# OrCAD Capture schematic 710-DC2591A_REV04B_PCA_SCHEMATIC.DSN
size Custom; note: EasySMU
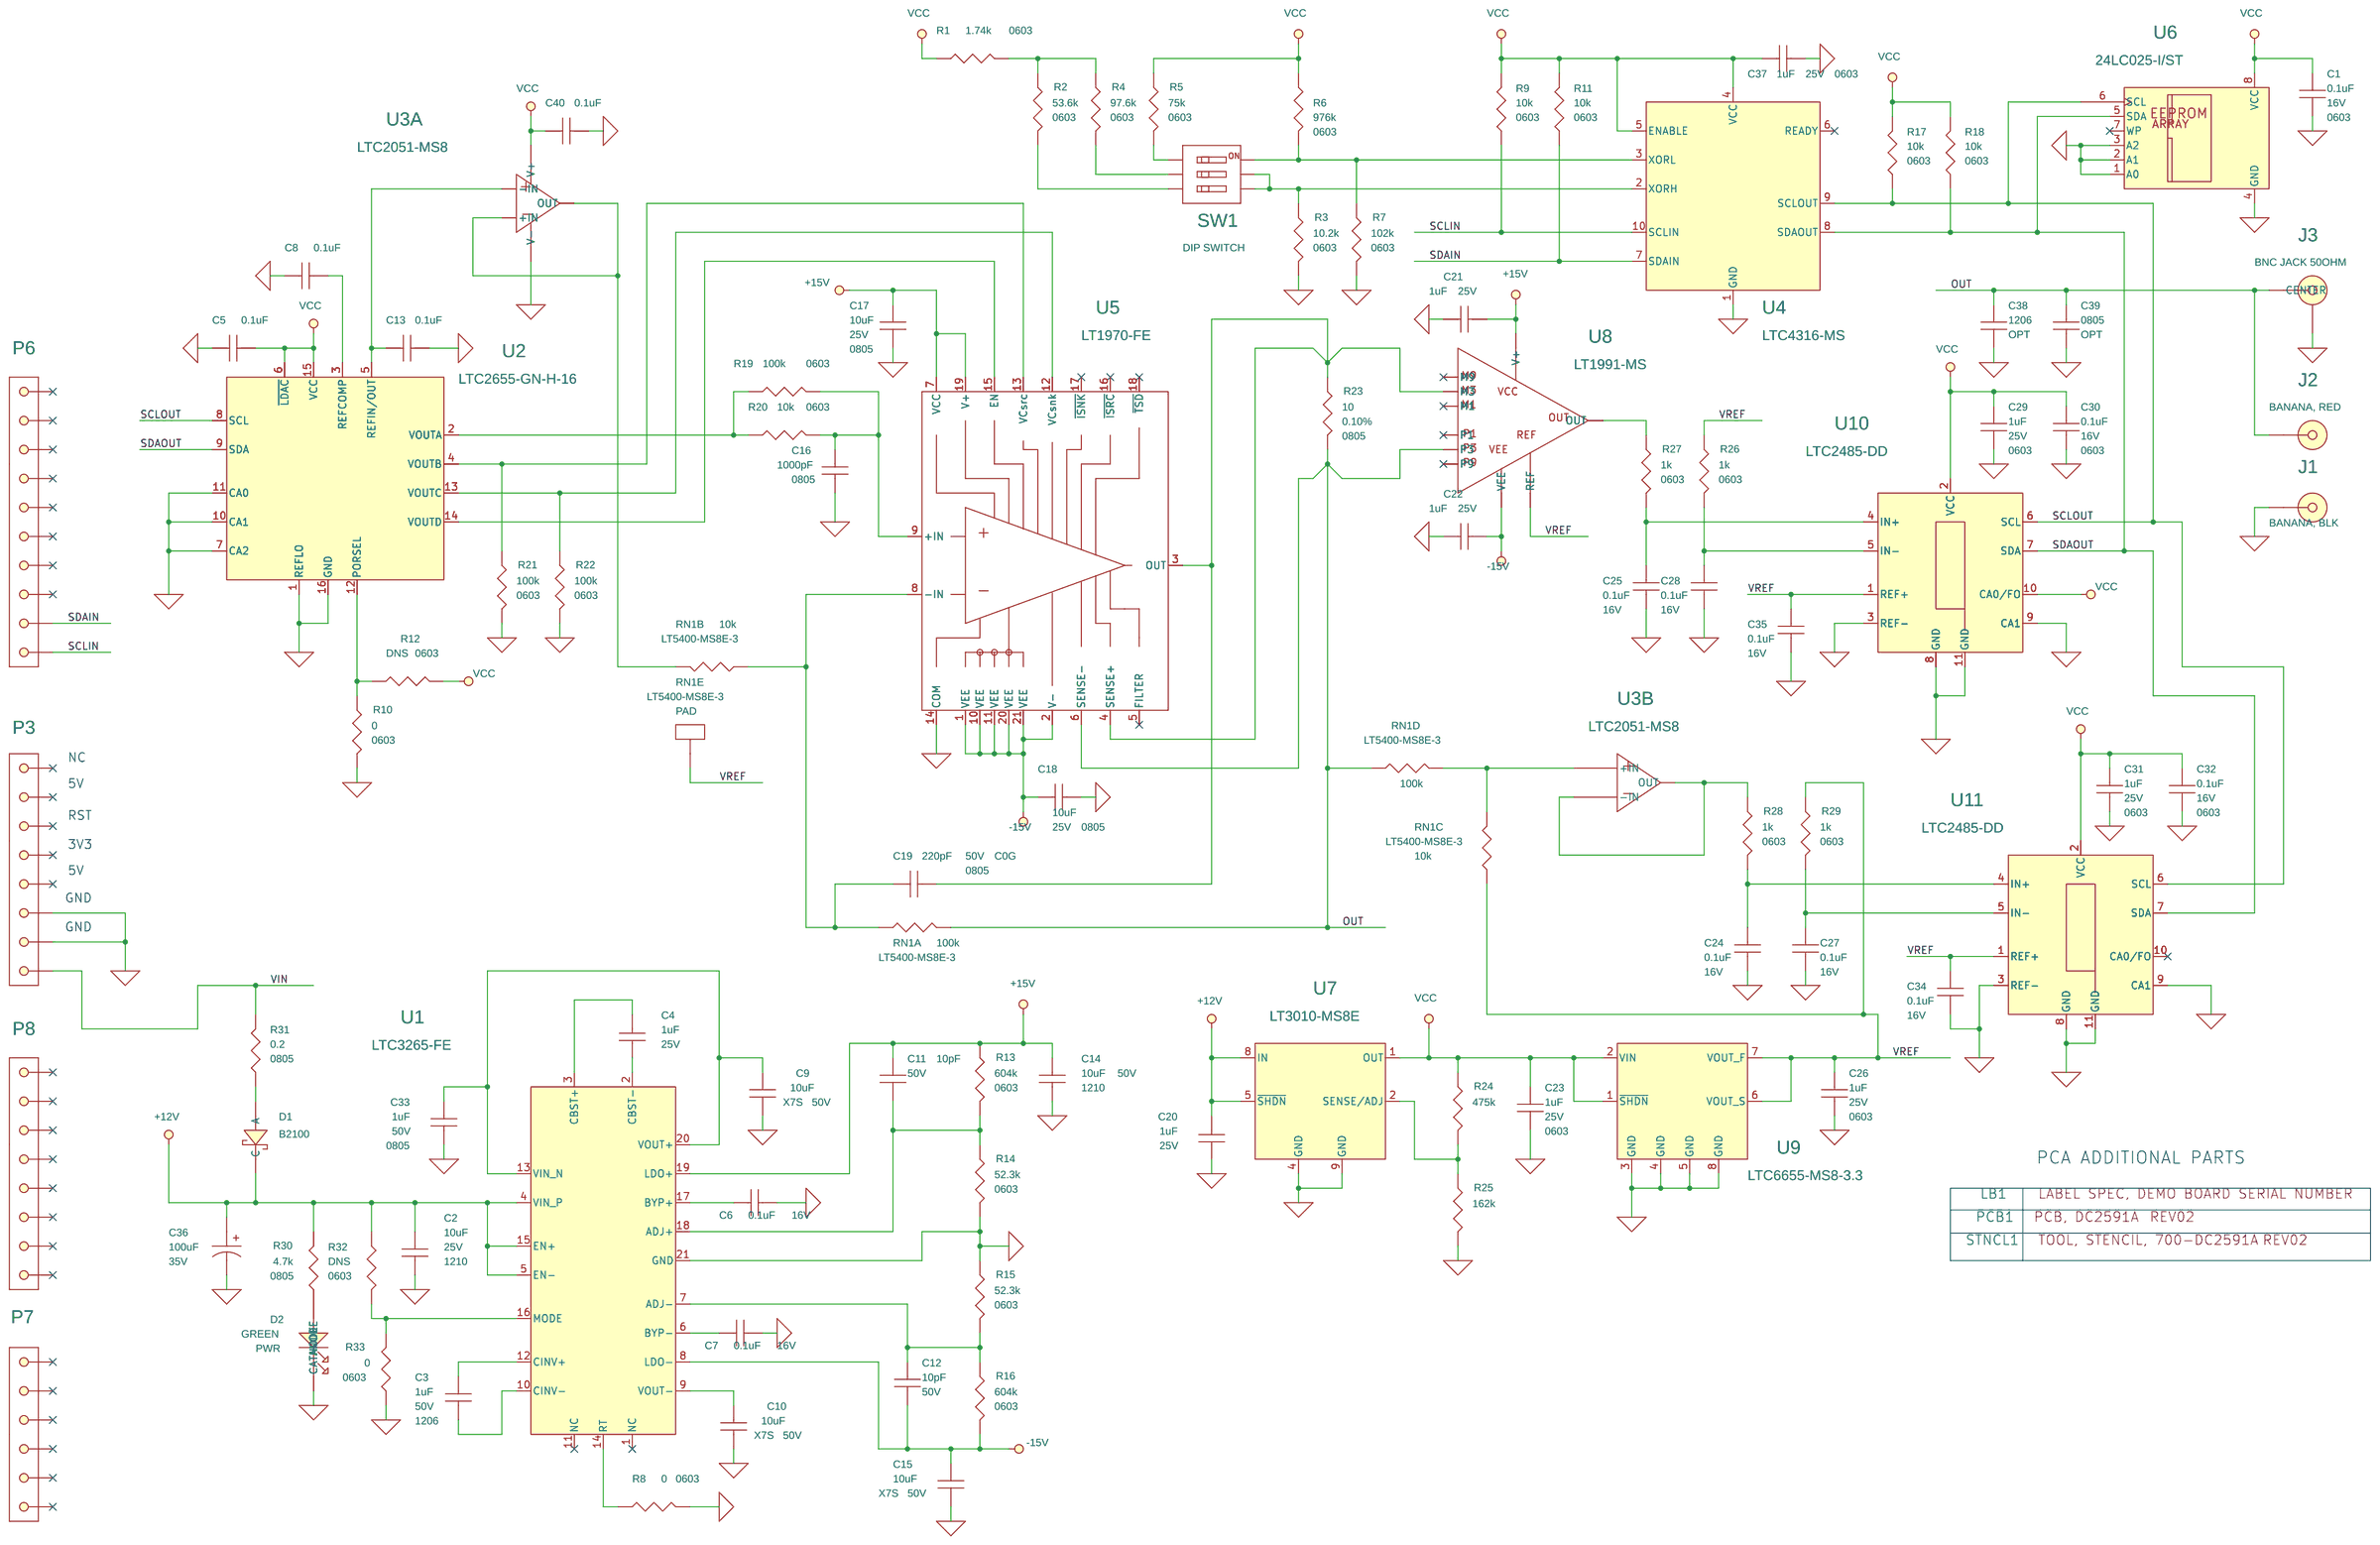
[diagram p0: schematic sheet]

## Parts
C1  0.1uF  [CC0603N]
C2  10uF  [CC1210N]
C3  1uF  [CC1206N]
C4  1uF  [CC0805N]
C5  0.1uF  [CC0603N]
C6  0.1uF  [CC0603N]
C7  0.1uF  [CC0603N]
C8  0.1uF  [CC0603N]
C9  10uF  [CC1210N]
C10  10uF  [CC1210N]
C11  10pF  [CC0603N]
C12  10pF  [CC0603N]
C13  0.1uF  [CC0603N]
C14  10uF  [CC1210N]
C15  10uF  [CC1210N]
C16  1000pF  [CC0805N]
C17  10uF  [CC0805N]
C18  10uF  [CC0805N]
C19  220pF  [CC0805N]
C20  1uF  [CC0805N]
C21  1uF  [CC0603N]
C22  1uF  [CC0603N]
C23  1uF  [CC0603N]
C24  0.1uF  [CC0603N]
C25  0.1uF  [CC0603N]
C26  1uF  [CC0603N]
C27  0.1uF  [CC0603N]
C28  0.1uF  [CC0603N]
C29  1uF  [CC0603N]
C30  0.1uF  [CC0603N]
C31  1uF  [CC0603N]
C32  0.1uF  [CC0603N]
C33  1uF  [CC0805N]
C34  0.1uF  [CC0603N]
C35  0.1uF  [CC0603N]
C36  100uF  [SUNCON_HVP_8X10.5]
C37  1uF  [CC0603N]
C38  OPT  [CC1206N]
C39  OPT  [CC0805N]
C40  0.1uF  [CC0603N]
D1  B2100  [DIODESINC-SMB]
D2  GREEN  [LED_0805]
J1  JACK SOCKET BLACK  [MULTI-CONTACT_SLB4-I/90]
J2  JACK SOCKET RED  [MULTI-CONTACT_SLB4-I/90]
J3  BNC JACK 50OHM  [MOLEX-73137-5003]
LB1  LABEL  [895-0154_REV01]
P3  HDR  [HD1X8-100]
P6  HDR  [HD1X10-100]
P7  HDR  [HD1X6-100]
P8  HDR  [HD1X8-100]
PCB1  PCB, DC2591A
R1  1.74k  [CR0603N]
R2  53.6k  [CR0603N]
R3  10.2k  [CR0603N]
R4  97.6k  [CR0603N]
R5  75k  [CR0603N]
R6  976k  [CR0603N]
R7  102k  [CR0603N]
R8  0  [CR0603N]
R9  10k  [CR0603N]
R10  0  [CR0603N]
R11  10k  [CR0603N]
R12  OPT  [CR0603N]
R13  604k  [CR0603N]
R14  52.3k  [CR0603N]
R15  52.3k  [CR0603N]
R16  604k  [CR0603N]
R17  10k  [CR0603N]
R18  10k  [CR0603N]
R19  100k  [CR0603N]
R20  10k  [CR0603N]
R21  100k  [CR0603N]
R22  100k  [CR0603N]
R23  10  [CR0805N]
R24  475k  [CR0805N]
R25  162k  [CR0805N]
R26  1k  [CR0603N]
R27  1k  [CR0603N]
R28  1k  [CR0603N]
R29  1k  [CR0603N]
R30  4.7k  [CR0805N]
R31  0.2  [CR0805N]
R32  OPT  [CR0603N]
R33  0  [CR0603N]
RN1  LT5400-MS8E-3  [LTC-MS8E-8-1662]  (sections A,B,C,D,E)
STNCL1  TOOL, STENCIL, 700-DC2591A
SW1  SPST  [CTS-219-3]
U1  LTC3265-FE  [LTC-FE-20-1663(CA)]
U2  LTC2655-GN-H-16  [LTC-GN-16-1641(GN16)]
U3  LTC2051-MS8  [LTC-MS8-8-1660]  (sections A,B)
U4  LTC4316-MS  [LTC-MS-10-1661]
U5  LT1970-FE  [LTC-FE-20-1663(CA)]
U6  24LC025-I/ST  [MICROCHIP-TSSOP-8]
U7  LT3010-MS8E  [LTC-MS8E-8-1662]
U8  LT1991-MS  [LTC-MS-10-1661]
U9  LTC6655-MS8-3.3  [LTC-MS8-8-1660]
U10  LTC2485-DD  [LTC-DD-10-1699]
U11  LTC2485-DD  [LTC-DD-10-1699]

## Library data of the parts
C1 C6 C7 C24 C25 C27 C28 C30 C32 C34 C35 = CAP: CAP.,0.1uF,X7R,16V,10%,0603; CLASS: DISCRETE; Dielectric Type: X7R; FPLIST: CC0603N,CC0603L,CC0603M; Manufacturer: MURATA; Manufacturer PN: GRM188R71C104KA01D; PART_NUMBER: 150-0018; Package Size: 0603; Package Type: SMD; Rated Voltage: 16V; Tolerance: 10%
C2 = CAP: CAP.,10uF,X7R,25V,10%,1210; CLASS: DISCRETE; Dielectric Type: X7R; FPLIST: CC1210N,CC1210L,CC1210M; Manufacturer: MURATA; Manufacturer PN: GRM32DR71E106KA12L; PART_NUMBER: 150-0282; Package Size: 1210; Rated Voltage: 25V; Tolerance: 10%
C3 = CAP: CAP.,1uF,X7R,50V,10%,1206; CLASS: DISCRETE; Dielectric Type: X7R; FPLIST: CC1206N,CC1206L,CC1206M; Manufacturer: MURATA; Manufacturer PN: GRM31MR71H105KA88L; PART_NUMBER: 150-3089; Package Size: 1206; Rated Voltage: 50V; Tolerance: 10%
C4 C20 = CAP: CAP.,1uF,X7R,25V,10%,0805; CLASS: DISCRETE; Dielectric Type: X7R; FPLIST: CC0805N,CC0805L,CC0805M; Manufacturer: AVX; Manufacturer PN: 08053C105KAT2A; PART_NUMBER: 150-3037; Package Size: 0805; Rated Voltage: 25V; Tolerance: 10%
C5 C8 C13 C40 = CAP: CAP.,0.1uF,X7R,16V,10%,0603; CLASS: DISCRETE; Dielectric Type: X7R; FPLIST: CC0603N,CC0603L,CC0603M; Manufacturer: AVX; Manufacturer PN: 0603YC104KAT2A; PART_NUMBER: 150-0164; Package Size: 0603; Package Type: SMD; Rated Voltage: 16V; Tolerance: 10%
C9 C10 C15 = CAP: CAP.,10uF,X7S,50V,10%,1210; CLASS: DISCRETE; Dielectric Type: X7S; Manufacturer: TDK; Manufacturer PN: C3225X7S1H106K250AB; PART_NUMBER: 150-3091; Package Size: 1210; Rated Voltage: 50V; Tolerance: 10%
C11 C12 = CAP: CAP.,10pF,NP0,50V,5%,0603; CLASS: DISCRETE; Dielectric Type: NP0; FPLIST: CC0603N,CC0603L,CC0603M; Manufacturer: NIC; Manufacturer PN: NMC0603NPO100J50TRPF; PART_NUMBER: 150-3504; Package Size: 0603; Rated Voltage: 50V; Tolerance: 5%
C14 = CAP: CAP.,10uF,X7R,50V,10%,1210; CLASS: DISCRETE; Dielectric Type: X7R; Manufacturer: MURATA; Manufacturer PN: GRM32ER71H106KA12L; PART_NUMBER: 150-3043; Package Size: 1210; Package Type: SMD; Rated Voltage: 50V; Tolerance: 10%
C16 = CAP: CAP.,1000pF,X7R,50V,5%,0805; CLASS: DISCRETE; Dielectric Type: X7R; FPLIST: CC0805N,CC0805L,CC0805M; Manufacturer: AVX; Manufacturer PN: 08055C102JAT2A; PART_NUMBER: 150-0582; Package Size: 0805; Rated Voltage: 50V; Tolerance: 5%
C17 C18 = CAP: CAP.,10uF,X5R,25V,10%,0805; CLASS: DISCRETE; Dielectric Type: X5R; FPLIST: CC0805N,CC0805L,CC0805M; Manufacturer: MURATA; Manufacturer PN: GRM21BR61E106KA73L; PART_NUMBER: 150-3405; Package Size: 0805; Package Type: SMD; Rated Voltage: 25V; Tolerance: 10%; UserField01: Thickness = 1.25 +/-0.15mm
C19 = CAP: CAP.,220pF,C0G,50V,5%,0805; CLASS: DISCRETE; Dielectric Type: C0G; FPLIST: CC0805N,CC0805L,CC0805M; Manufacturer: AVX; Manufacturer PN: 08055A221JAT2A; PART_NUMBER: 150-3424; Package Size: 0805; Rated Voltage: 50V; Tolerance: 5%
C21-C23 C26 C29 C31 C37 = CAP: CAP.,1uF,X5R,25V,10%,0603; CLASS: DISCRETE; Dielectric Type: X5R; FPLIST: CC0603N,CC0603L,CC0603M; Manufacturer: MURATA; Manufacturer PN: GRM188R61E105KA12D; PART_NUMBER: 150-0247; Package Size: 0603; Rated Voltage: 25V; Tolerance: 10%
C33 = CAP: CAP.,1uF,X7R,50V,10%,0805; CLASS: DISCRETE; Dielectric Type: X7R; FPLIST: CC0805N,CC0805L,CC0805M; Manufacturer: MURATA; Manufacturer PN: GRM21BR71H105KA12L; PART_NUMBER: 150-3335; Package Size: 0805; Rated Voltage: 50V; Tolerance: 10%
C36 = CAP_P: CAP.,100uF,ALUM.,35V,20%,SMD 8x10.5mm,HVP Series; CLASS: DISCRETE; Dielectric Type: ALUM.; Manufacturer: SUN ELECTRONIC INDUSTRIES CORP; Manufacturer PN: 35HVP100M; PART_NUMBER: 150-2315; Package Size: SMD 8x10.5mm; Rated Voltage: 35V; Tolerance: 20%; UserField01: HVP Series
C38 = CAP: CAP., OPTION, 1206; CLASS: DISCRETE; FPLIST: CC1206N,CC1206L,CC1206M; PART_NUMBER: 150-3160; Package Size: 1206; Package Type: SMD
C39 = CAP: CAP., OPTION, 0805; CLASS: DISCRETE; FPLIST: CC0805N,CC0805L,CC0805M; PART_NUMBER: 150-3036; Package Size: 0805; Package Type: SMD
D1 = DIODE_SCHOTTKY_A: DIODE,SCHOTTKY,100V,2A,SMB,AECQ10x; CLASS: DISCRETE; Manufacturer: DIODES INC; Manufacturer PN: B2100-13-F; PART_NUMBER: 210-0088; Package Size: SMB; Package Type: SMB; Rated Voltage: 100V
D2 = LED: LED,GREEN,DIFFUSED,0805; CLASS: DISCRETE; Manufacturer: BROADCOM LIMITED; Manufacturer PN: HSMG-C170; PART_FIELD_1: PWR; PART_NUMBER: 270-0060; Package Type: 0805
J1 = BANANA_JACK: CONN.,JACK SOCKET BLACK,FEMALE,1 POS,33mm X 12mm,THT HOLE; CLASS: IO; Manufacturer: MULTI-CONTACT; Manufacturer PN: 23.3200-21; PART_FIELD_01: BANANA, BLK; PART_NUMBER: 250-0628
J2 = BANANA_JACK: CONN.,JACK SOCKET RED,FEMALE,1 POS,33mm X 12mm,THT-HOLE; CLASS: IO; Manufacturer: MULTI-CONTACT; Manufacturer PN: 23.3200-22; PART_FIELD_01: BANANA, RED; PART_NUMBER: 250-0627
J3 = BNC_2-PIN: CONN.,BNC JACK 50OHM,FEMALE,35.18mm x 13.2mm,THT, RA; CLASS: IO; Manufacturer: MOLEX; Manufacturer PN: 73137-5003; PART_NUMBER: 250-0634
LB1 = BLANK_LABEL: LABEL SPEC, DEMO BOARD SERIAL NUMBER; Manufacturer: BRADY; Manufacturer PN: THT-96-717-10; PART_NUMBER: 895-0154
P3 P8 = HDR1X8: CONN.,HDR,RECEPT,1X8,2.54mm,THT STR; CLASS: IO; Manufacturer: SAMTEC; Manufacturer PN: SSQ-108-04-G-S; PART_NUMBER: 250-0635
P6 = HDR1X10: CONN.,HDR,RECEPT,1X10,2.54mm,THT STR; CLASS: IO; Manufacturer: SAMTEC; Manufacturer PN: SSQ-110-04-G-S; PART_NUMBER: 250-0636
P7 = HDR1X6: CONN.,HDR,RECEPT,1X6,2.54mm,THT STR; CLASS: IO; Manufacturer: SAMTEC; Manufacturer PN: SSQ-106-04-G-S; PART_NUMBER: 250-0637
PCB1 = BLANK_PCB_PART: BOM Notes: REV02; CLASS: DISCRETE; Manufacturer: MAO BANG; Manufacturer PN: 600-DC2591A; PART_NUMBER: 600-DC2591A
R1 = RES: RES.,1.74k OHMS,1%,1/10W,0603; CLASS: DISCRETE; FPLIST: CR0603N,CR0603L,CR0603M; Manufacturer: YAGEO; Manufacturer PN: 9C06031A1741FKHFT; PART_NUMBER: 100-0135; Package Size: 0603; Rated Power: 1/10W; Tolerance: 1%
R2 = RES: RES.,53.6k OHMS,1%,1/10W,0603; CLASS: DISCRETE; FPLIST: CR0603N,CR0603L,CR0603M; Manufacturer: KOA SPEER; Manufacturer PN: RK73H1JTTD5362F; PART_NUMBER: 100-0233; Package Size: 0603; Rated Power: 1/10W; Temperature Coefficient: 100ppm/C; Tolerance: 1%
R3 = RES: RES.,10.2k OHMS,1%,1/10W,0603; CLASS: DISCRETE; Manufacturer: VISHAY; Manufacturer PN: CRCW060310K2FKEA; PART_NUMBER: 100-0627; Package Size: 0603; Rated Power: 1/10W; Temperature Coefficient: +/-100PPM; Tolerance: 1%
R4 = RES: RES.,97.6k OHMS,1%,1/10W,0603; CLASS: DISCRETE; Manufacturer: VISHAY; Manufacturer PN: CRCW060397K6FKEA; PART_NUMBER: 100-0628; Package Size: 0603; Rated Power: 1/10W; Temperature Coefficient: +/-100PPM; Tolerance: 1%
R5 = RES: RES.,AEC-Q200,75k OHMS,0.1%,1/16W,0603; CLASS: DISCRETE; FPLIST: CR0603N,CR0603L,CR0603M; Manufacturer: SUSUMU CO LTD; Manufacturer PN: RG1608P-753-B-T5.; PART_NUMBER: 100-0159; Package Size: 0603; Rated Power: 1/16W; Temperature Coefficient: 25ppm/C; Tolerance: 0.10%
R6 = RES: RES.,976k OHMS,1%,1/10W,0603; CLASS: DISCRETE; FPLIST: CR0603N,CR0603L,CR0603M; Manufacturer: YAGEO; Manufacturer PN: RC0603FR-07976KL; PART_NUMBER: 100-2619; Package Size: 0603; Rated Power: 1/10W; Temperature Coefficient: 100ppm/C; Tolerance: 1%
R7 = RES: RES.,102k OHMS,1%,1/10W,0603; CLASS: DISCRETE; FPLIST: CR0603N,CR0603L,CR0603M; Manufacturer: NIC; Manufacturer PN: NRC06F1023TRF; PART_NUMBER: 100-2726; Package Size: 0603; Rated Power: 1/10W; Temperature Coefficient: 100ppm/C; Tolerance: 1%
R8 R10 R33 = RES: RES.,0 OHM,1/10W,0603; CLASS: DISCRETE; FPLIST: CR0603N,CR0603L,CR0603M; Manufacturer: VISHAY; Manufacturer PN: CRCW06030000Z0EA; PART_NUMBER: 100-0009; Package Size: 0603; Rated Power: 1/10W
R9 R11 R17 R18 R20 = RES: RES.,10k OHMS,1%,1/10W,0603; CLASS: DISCRETE; FPLIST: CR0603N,CR0603L,CR0603M; Manufacturer: NIC; Manufacturer PN: NRC06F1002TRF; PART_NUMBER: 100-2532; Package Size: 0603; Rated Power: 1/10W; Temperature Coefficient: 100ppm/C; Tolerance: 1%
R12 R32 = RES: RES., OPTION, 0603; CLASS: DISCRETE; FPLIST: CR0603N,CR0603L,CR0603M; PART_FIELD_1: DNS; PART_NUMBER: 100-2374; Package Size: 0603
R13 R16 = RES: RES.,604k OHMS,1%,1/10W,0603; CLASS: DISCRETE; FPLIST: CR0603N,CR0603L,CR0603M; Manufacturer: VISHAY; Manufacturer PN: CRCW0603604KFKEA; PART_NUMBER: 100-2679; Package Size: 0603; Rated Power: 1/10W; Temperature Coefficient: 100ppm; Tolerance: 1%
R14 R15 = RES: RES.,52.3k OHMS,1%,1/10W,0603; CLASS: DISCRETE; FPLIST: CR0603N,CR0603L,CR0603M; Manufacturer: VISHAY; Manufacturer PN: CRCW060352K3FKEA; PART_NUMBER: 100-0346; Package Size: 0603; Rated Power: 1/10W; Temperature Coefficient: 100ppm/C; Tolerance: 1%
R19 R21 R22 = RES: RES.,100k OHMS,1%,1/10W,0603; CLASS: DISCRETE; FPLIST: CR0603N,CR0603L,CR0603M; Manufacturer: NIC; Manufacturer PN: NRC06F1003TRF; PART_NUMBER: 100-0343; Package Size: 0603; Rated Power: 1/10W; Temperature Coefficient: 100ppm; Tolerance: 1%
R23 = RES: RES.,CURRENT SENSE,10 OHMS,0.1%,1/8W,0805; CLASS: DISCRETE; Manufacturer: BOURNS; Manufacturer PN: CRT0805-BY-10R0ELF; PART_NUMBER: 100-0629; Package Size: 0805; Rated Power: 1/8W; Temperature Coefficient: +/-25PPM; Tolerance: 0.10%
R24 = RES: RES.,475k OHMS,1%,1/8W,0805; CLASS: DISCRETE; Manufacturer: YAGEO; Manufacturer PN: RC0805FR-07475KL; PART_NUMBER: 100-0630; Package Size: 0805; Rated Power: 1/8W; Temperature Coefficient: +/-100PPM; Tolerance: 1%
R25 = RES: RES.,162k OHMS,1%,1/8W,0805; CLASS: DISCRETE; Manufacturer: YAGEO; Manufacturer PN: RC0805FR-07162KL; PART_NUMBER: 100-0631; Package Size: 0805; Rated Power: 1/8W; Temperature Coefficient: PPM; Tolerance: 1%
R26-R29 = RES: RES.,1k OHM,1%,1/10W,0603; CLASS: DISCRETE; FPLIST: CR0603N,CR0603L,CR0603M; Manufacturer: NIC; Manufacturer PN: NRC06F1001TRF; PART_NUMBER: 100-2422; Package Size: 0603; Rated Power: 1/10W; Temperature Coefficient: 100ppm; Tolerance: 1%
R30 = RES: RES.,4.7k OHMS,5%,1/8W,0805; CLASS: DISCRETE; FPLIST: CR0805N,CR0805L,CR0805M; Manufacturer: PANASONIC; Manufacturer PN: ERJ6GEYJ472V; PART_NUMBER: 100-2602; Package Size: 0805; Rated Power: 1/8W; Temperature Coefficient: 200ppm/C; Tolerance: 5%
R31 = RES: RES.,NO ALTERNATE MFR P/N ALLOWED,0.2 OHMS,5%,1/4W,0805; CLASS: DISCRETE; Manufacturer: PANASONIC; Manufacturer PN: ERJS6SJR20V; PART_NUMBER: 100-2560; Package Size: 0805; Rated Power: 1/4W; Temperature Coefficient: 150ppm/C; Tolerance: 5%
RN1 = LT5400-MS8E-X_A-E: IC,QUAD RESISTOR NETWORK,8-pin MS8E; CLASS: IC; Manufacturer: LINEAR TECHNOLOGY; Manufacturer PN: LT5400AIMS8E-3#PBF; PART_FIELD_1: 100k; PART_NUMBER: LT5400AIMS8E-3#PBF; Package Size: MS8E; Package Type: 8-pin MS8E; FIRST_PART_FIELD: 100k
STNCL1 = BLANK_STENCIL_PART: BOM Notes: REV02; CLASS: DISCRETE; Manufacturer: LINEAR TECHNOLOGY; Manufacturer PN: 830-DC2591A; PART_NUMBER: 830-DC2591A
SW1 = DIP_SW_3POS: SWITCH,SLIDE DIP,SPST,100MA,20V,THT; CLASS: DISCRETE; Manufacturer: CTS; Manufacturer PN: 219-3MST; PART_FIELD_1: DIP SWITCH; PART_NUMBER: 430-0068; Package Size: 0.358" (9.09mm)
U1 = LTC3265-FE: IC SWITCHED CAPACITOR INVERTING REGULATOR, TSSOP-20; CLASS: IC; Manufacturer: LINEAR TECHNOLOGY; Manufacturer PN: LTC3265IFE#PBF; PART_NUMBER: LTC3265IFE#PBF; Package Size: 20-TSSOP; Package Type: 20-pin TSSOP
U2 = LTC2655-GN-H-X: QUAD 16-BIT DAC; CLASS: IC; Manufacturer: LINEAR TECHNOLOGY; Manufacturer PN: LTC2655BIGN-H16#PBF; PART_NUMBER: LTC2655BIGN-H16#PBF; Package Type: 16-pin NARROW SSOP
U3 = LTC2051-MS8: DUAL ZERO-DRIFT OP AMP; CLASS: IC; Manufacturer: LINEAR TECHNOLOGY; Manufacturer PN: LTC2051IMS8#PBF; PART_NUMBER: LTC2051IMS8#PBF; Package Size: MSOP; Package Type: 8pin MSOP
U4 = LTC4316-MS: IC,I2C/SMBUS TRANSLATOR,MS10; CLASS: IC; Manufacturer: LINEAR TECHNOLOGY; Manufacturer PN: LTC4316IMS#PBF; PART_NUMBER: LTC4316IMS#TRPBF; Package Size: TSOT-23; Package Type: MS10
U5 = LT1970-FE: POWER OP-AMP; CLASS: IC; Manufacturer: LINEAR TECHNOLOGY; Manufacturer PN: LT1970AIFE#PBF; PART_NUMBER: LT1970AIFE#PBF; Package Size: 20-TSSOP; Package Type: 20-pin TSSOP
U6 = 24LC025-I_ST_TSSOP-8_C: IC, MEMORY,EEPROM,2Kb (256x8),TSSOP-8,400kHz; CLASS: IC; Manufacturer: Microchip; PART_NUMBER: 380-0087; Package Size: TSSOP-8; Package Type: TSSOP-8
U7 = LT3010-MS8E-X: IC,LDO uPWR LINEAR REG.,MSOP-8; CLASS: IC; Manufacturer: LINEAR TECHNOLOGY; Manufacturer PN: LT3010EMS8E#PBF; PART_NUMBER: LT3010EMS8E#PBF; Package Size: 20-TSSOP; Package Type: MSOP-8
U8 = LT1991-MS: GAIN-SELECTABLE AMPLIFIER; CLASS: IC; Manufacturer: LINEAR TECHNOLOGY; Manufacturer PN: LT1991AIMS#PBF; PART_NUMBER: LT1991AIMS#PBF; Package Size: MS-10; Package Type: 10-pin MSOP
U9 = LTC6655-MS8-X_ALT1: IC, VOLTAGE REFERENCE, MSOP; CLASS: IC; Manufacturer: LINEAR TECHNOLOGY; Manufacturer PN: LTC6655BHMS8-3.3#PBF; PART_NUMBER: LTC6655BHMS8-3.3#TRPBF; Package Size: MS8; Package Type: 8-pin MSOP
U10 U11 = LTC2485-DD: 24-BiT Delta Sigma ADC; CLASS: IC; Manufacturer: LINEAR TECHNOLOGY; Manufacturer PN: LTC2485IDD#PBF; PART_NUMBER: LTC2485IDD#PBF; Package Type: 10-pin DFN

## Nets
+12V: C2.1 C20.2 C36.1 D1.1(C) R30.1 R32.1 U1.4(VIN_P) U1.5(EN-) U1.15(EN+) U7.5(~{SHDN}) U7.8(IN)
+15V: C11.1 C14.1 C17.1 C21.2 R13.1 U1.19(LDO+) U5.7(VCC) U5.19(V+) U8.7(V+)
-15V: C12.2 C15.1 C18.1 C22.2 R16.2 U1.8(LDO-) U5.1(VEE) U5.2(V-) U5.10(VEE) U5.11(VEE) U5.20(VEE) U5.21(VEE) U8.4(VEE)
GND_SIGNAL: C1.2 C2.2 C5.1 C6.2 C7.2 C8.1 C9.2 C10.2 C13.2 C14.2 C15.2 C16.2 C17.2 C18.2 C20.1 C21.1 C22.1 C23.2 C24.2 C25.2 C26.2 C27.2 C28.2 C29.2 C30.2 C31.2 C32.2 C33.2 C34.2 C35.2 C36.2 C37.2 C38.2 C39.2 C40.2 D2.1(CATHODE) J1.1 J3.2 P3.6 P3.7 R3.2 R7.2 R8.2 R10.2 R14.2 R15.1 R21.2 R22.2 R25.2 R33.2 U1.21(GND) U2.1(REFLO) U2.7(CA2) U2.10(CA1) U2.11(CA0) U2.16(GND) U3.4(V-) U4.1(GND) U5.14(COM) U6.1(A0) U6.2(A1) U6.3(A2) U6.4(GND) U7.4(GND) U7.9(GND) U9.3(GND) U9.4(GND) U9.5(GND) U9.8(GND) U10.3(REF-) U10.8(GND) U10.9(CA1) U10.11(GND) U11.3(REF-) U11.8(GND) U11.9(CA1) U11.11(GND)
VCC: C1.1 C5.2 C23.1 C29.1 C30.1 C31.1 C32.1 C37.1 C40.1 R1.1 R5.1 R6.1 R9.2 R11.2 R12.2 R17.2 R18.2 R24.1 U2.6(~{LDAC}) U2.15(VCC) U3.8(V+) U4.4(VCC) U4.5(ENABLE) U6.8(VCC) U7.1(OUT) U9.1(~{SHDN}) U9.2(VIN) U10.2(VCC) U10.10(CA0/FO) U11.2(VCC)
VIN: P3.8 R31.2
OUT: C38.1 C39.1 J2.1 J3.1(CENTER) R23.2 RN1.1 RN1.4 U5.6(SENSE-) U8.2(P3)
SCLIN: P6.10 R9.1 U4.10(SCLIN)
SCLOUT: R17.1 U2.8(SCL) U4.9(SCLOUT) U6.6(SCL) U10.6(SCL) U11.6(SCL)
SDAIN: P6.9 R11.1 U4.7(SDAIN)
SDAOUT: R18.1 U2.9(SDA) U4.8(SDAOUT) U6.5(SDA) U10.7(SDA) U11.7(SDA)
VREF: C26.1 C34.1 C35.1 R26.1 R29.1 RN1.3 RN1.9 U8.5(REF) U9.6(VOUT_S) U9.7(VOUT_F) U10.1(REF+) U11.1(REF+)
N827852: C13.1 U2.5(REFIN/OUT) U3.3(-IN)
N827859: RN1.2 U3.1(OUT) U3.2(+IN)
N828150: C8.2 U2.3(REFCOMP)
N828504: U2.14(VOUTD) U5.15(EN)
N828692: C19.1 RN1.7 RN1.8 U5.8(-IN)
N829535: C19.2 R23.1 U5.3(OUT) U5.4(SENSE+) U8.9(M3)
N832282: R22.1 U2.13(VOUTC) U5.12(VCsnk)
N832471: R21.1 U2.4(VOUTB) U5.13(VCsrc)
N832594: R19.1 R20.1 U2.2(VOUTA)
N832697: C16.1 R19.2 R20.2 U5.9(+IN)
N833201: R10.1 R12.1 U2.12(PORSEL)
N833769: C4.2 U1.3(CBST+)
N833810: C4.1 U1.2(CBST-)
N834660: R8.1 U1.14(RT)
N834976: C9.1 C33.1 U1.13(VIN_N) U1.20(VOUT+)
N835128: C3.1 U1.12(CINV+)
N835135: C3.2 U1.10(CINV-)
N835199: R32.2 R33.1 U1.16(MODE)
N838050: C6.1 U1.17(BYP+)
N838227: C11.2 R13.2 R14.1 U1.18(ADJ+)
N838920: C12.1 R15.2 R16.1 U1.7(ADJ-)
N839750: C7.1 U1.6(BYP-)
N841725: C10.1 U1.9(VOUT-)
N850889: R27.1 U8.6(OUT)
N850909: C25.1 R27.2 U10.4(IN+)
N850916: C28.1 R26.2 U10.5(IN-)
N858102: R24.2 R25.1 U7.2(SENSE/ADJ)
N867916: RN1.5 RN1.6 U3.5(+IN)
N870137: R28.1 U3.6(-IN) U3.7(OUT)
N870679: C24.1 R28.2 U11.4(IN+)
N870688: C27.1 R29.2 U11.5(IN-)
N876711: R3.1 SW1.4 SW1.5 U4.2(XORH)
N880577: R6.2 R7.1 SW1.6 U4.3(XORL)
N883246: R5.2 SW1.1
N885546: R4.2 SW1.2
N885551: R1.2 R2.1 R4.1
N885969: R2.2 SW1.3
N897216: D1.2(A) R31.1
N981023: D2.2(ANODE) R30.2

Not connected (* = marked no-connect by the designer): P3 1* 2* 3* 4* 5*; P6 1* 2* 3* 4* 5* 6* 7* 8*; P7 1* 2* 3* 4* 5* 6*; P8 1* 2* 3* 4* 5* 6* 7* 8*; U1 1(NC)* 11(NC)*; U4 6(READY)*; U5 5(FILTER)* 16(~{ISRC})* 17(~{ISNK})* 18(~{TSD})*; U6 7(WP)*; U8 1(P1)* 3(P9)* 8(M9)* 10(M1)*; U11 10(CA0/FO)*

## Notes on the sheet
- NC
- 5V
- RST
- 3V3
- 5V
- GND
- GND
- PCA ADDITIONAL PARTS
